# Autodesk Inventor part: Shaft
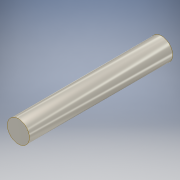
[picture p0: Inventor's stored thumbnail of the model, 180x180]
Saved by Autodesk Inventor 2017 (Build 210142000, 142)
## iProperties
Created: 2020-03
Part Number: Shaft
Material: Titanium
Document SubType Name: Modeling
Designer: user
Density: 4.51 g/cm^3
Appearance: Titanium
Author: user
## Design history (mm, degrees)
sketch "Sketch1"
  geometry: C1 r 2 at (0, 0); 1 further point
  constraints: 1 centre point, 1 coincident
  dimensions: "d0" = 4 diameter of C1
extrude "Extrusion1" new body sketch "Sketch1" stored distance "d1" = 26; taper "d2" = 0 deg
body "Solid1"
